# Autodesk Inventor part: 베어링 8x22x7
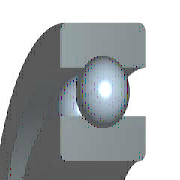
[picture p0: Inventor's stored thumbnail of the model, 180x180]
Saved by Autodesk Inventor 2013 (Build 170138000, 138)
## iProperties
IsCustomPart: 1
Created: 2012-02
Part Number: 베어링 8x22x7
Material: 강철, 연강
Description: 깊은 그루브 볼 베어링
Document SubType Name: Modeling
Standard: KS B 2023
Designer: mduedu
Standards Organization: KS
Language: ko-KR
Size Designation: 608 - 8 x 22 x 7
Categories: <MemberInstance><Categories><Category DisplayName="샤프트 부품" InternalName="7f7aeb1f-a693-4053-b835-cee3144e0d98" Mnemonic="SHFT"><Category DisplayName="베어링" Inter
Density: 1 g/cm^3
Author: mduedu
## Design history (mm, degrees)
sketch "스케치" dims "d0" = 3.64 (= -0.26 x WD + 0.26 x BD)
  geometry: L1 (1.68, 7.5)-(5.32, 7.5); L2 (3.5, 7.5)-(3.5, 5.68); L3 (3.5, 7.5)-(3.5, 9.32); L4 (2.148, 6.282)-(0, 6.282); L5 (0, 4)-(7, 4); L6 (2.148, 8.718)-(0, 8.718); L7 (0, 11)-(7, 11); L8 (7, 4)-(7, 6.282); L9 (4.852, 6.282)-(7, 6.282); L10 (4.852, 8.718)-(7, 8.718); L11 (7, 11)-(7, 8.718); L12 (-1.4, 0)-(8.4, 0) reference; L13 (0, -0.3)-(0, 5.3) reference
  constraints: 22 end point, 4 point on line, 2 collinear, 2 perpendicular, 2 symmetric about line, 1 midpoint, 1 parallel, 14 other
  dimensions: "d9" = 8 diameter of L5 L12 (= WD); "d11" = 22 diameter of L7 L12 (= BD); "d12" = 7 distance between parallel lines of L8 L13 (= KB); "d13" = 12.564 diameter of L9 L12 (= 0.326 x BD + 0.674 x WD)
revolve "본체" stored, may be unused: angle "d6" = 90 deg
revolve "볼" stored, may be unused: angle "d7" = 90 deg
pattern_circular "IDS_ARRAYBALL[SIMPL:T]" dims angle "d3" = 360 deg
body "Solid1"
fillet "모깎기1" dims "d1" = 0.3 (= KRS)
other parameters: "WD" = 8 [user parameter; used in 5 equation terms], "BD" = 22 [user parameter; used in 5 equation terms], "KB" = 7 [user parameter; used in 1 equation term], "KRS" = 0.3 [user parameter; used in 1 equation term], "d4" = 0, "d5" = 0, "d8" = 0, "d14" = 0, "d15" = 0, "BBA" = 0 [user parameter], "BC0" = 1370000 [user parameter], "BC" = 3250000 [user parameter], "BR" = 11 (= 0.5 x BD) [user parameter], "WR" = 4 (= 0.5 x WD) [user parameter]
